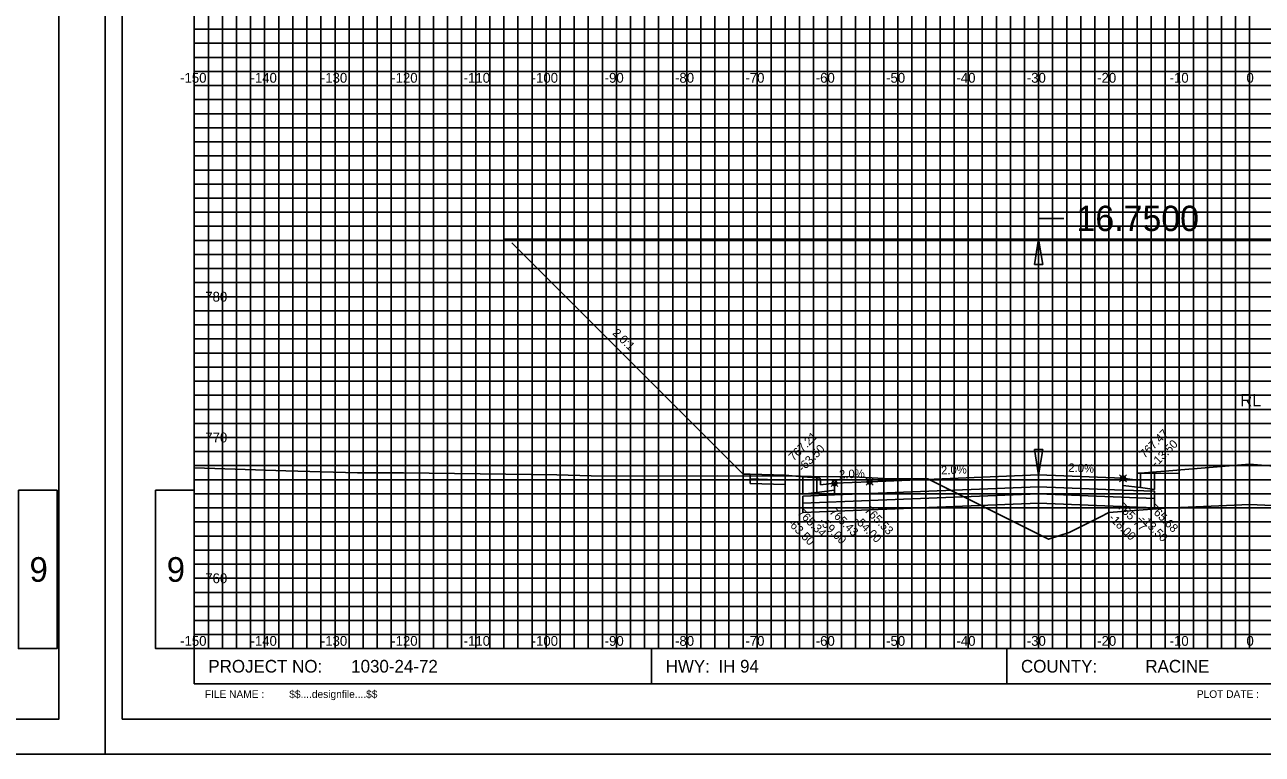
# Model space of a CAD drawing. Extents: x 578243 to 601557, y 174899 to 175559.
# Drawn here: x 600865.7 to 601041.6, y 174898.8 to 175002.4 of the extents above; entities that cross this region are included whole.
import ezdxf

# ---------------------------------------------------------------- set-up
doc = ezdxf.new("R2010")
doc.units = 0
for name, color, linetype in [('E_PROF_Grid', 7, 'Continuous'), ('E_PROF_GridMin', 7, 'Continuous'), ('P_CRDR_Label', 7, 'Continuous'), ('P_CRDR_Link', 7, 'Continuous'), ('P_E_XS_Ground', 7, 'Continuous'), ('P_RW_SlopeIntercepts', 7, 'Continuous'), ('P_XS_Text', 7, 'Continuous'), ('PLT_Sheet_Border', 7, 'Continuous'), ('PLT_Sheet_Info', 7, 'Continuous')]:
    doc.layers.add(name, color=color, linetype=linetype)

msp = doc.modelspace()

# ---------------------------------------------------------------- linework, layer by layer
at = {"layer": 'E_PROF_Grid'}
for p, q in [((600899.84, 174913.8), (600899.84, 175108.8)), ((600909.84, 174913.8), (600909.84, 175108.8)), ((600919.84, 174913.8), (600919.84, 175108.8)), ((600929.84, 174913.8), (600929.84, 175108.8)), ((600939.84, 174913.8), (600939.84, 175108.8)), ((600949.84, 174913.8), (600949.84, 175108.8)), ((600959.84, 174913.8), (600959.84, 175108.8)), ((600969.84, 174913.8), (600969.84, 175108.8)), ((600979.84, 174913.8), (600979.84, 175108.8)), ((600989.84, 174913.8), (600989.84, 175108.8)), ((600999.84, 174913.8), (600999.84, 175108.8)), ((601009.84, 174913.8), (601009.84, 175108.8)), ((601019.84, 174913.8), (601019.84, 175108.8)), ((601029.84, 174913.8), (601029.84, 175108.8)), ((601039.84, 174913.8), (601039.84, 175108.8)), ((600889.84, 174993.8), (601204.84, 174993.8)), ((600889.84, 174983.8), (601204.84, 174983.8)), ((600889.84, 174973.8), (601204.84, 174973.8)), ((600889.84, 174963.8), (601204.84, 174963.8)), ((600889.84, 174953.8), (601204.84, 174953.8)), ((600889.84, 174943.8), (601204.84, 174943.8)), ((600889.84, 174933.8), (601204.84, 174933.8)), ((600889.84, 174923.8), (601204.84, 174923.8))]:
    msp.add_line(p, q, dxfattribs=at)
at = {"layer": 'E_PROF_GridMin'}
for p, q in [((600891.84, 174913.8), (600891.84, 175108.8)), ((600893.84, 174913.8), (600893.84, 175108.8)), ((600895.84, 174913.8), (600895.84, 175108.8)), ((600897.84, 174913.8), (600897.84, 175108.8)), ((600901.84, 174913.8), (600901.84, 175108.8)), ((600903.84, 174913.8), (600903.84, 175108.8)), ((600905.84, 174913.8), (600905.84, 175108.8)), ((600907.84, 174913.8), (600907.84, 175108.8)), ((600911.84, 174913.8), (600911.84, 175108.8)), ((600913.84, 174913.8), (600913.84, 175108.8)), ((600915.84, 174913.8), (600915.84, 175108.8)), ((600917.84, 174913.8), (600917.84, 175108.8)), ((600921.84, 174913.8), (600921.84, 175108.8)), ((600923.84, 174913.8), (600923.84, 175108.8)), ((600925.84, 174913.8), (600925.84, 175108.8)), ((600927.84, 174913.8), (600927.84, 175108.8)), ((600931.84, 174913.8), (600931.84, 175108.8)), ((600933.84, 174913.8), (600933.84, 175108.8)), ((600935.84, 174913.8), (600935.84, 175108.8)), ((600937.84, 174913.8), (600937.84, 175108.8)), ((600941.84, 174913.8), (600941.84, 175108.8)), ((600943.84, 174913.8), (600943.84, 175108.8)), ((600945.84, 174913.8), (600945.84, 175108.8)), ((600947.84, 174913.8), (600947.84, 175108.8)), ((600951.84, 174913.8), (600951.84, 175108.8)), ((600953.84, 174913.8), (600953.84, 175108.8)), ((600955.84, 174913.8), (600955.84, 175108.8)), ((600957.84, 174913.8), (600957.84, 175108.8)), ((600961.84, 174913.8), (600961.84, 175108.8)), ((600963.84, 174913.8), (600963.84, 175108.8)), ((600965.84, 174913.8), (600965.84, 175108.8)), ((600967.84, 174913.8), (600967.84, 175108.8)), ((600971.84, 174913.8), (600971.84, 175108.8)), ((600973.84, 174913.8), (600973.84, 175108.8)), ((600975.84, 174913.8), (600975.84, 175108.8)), ((600977.84, 174913.8), (600977.84, 175108.8)), ((600981.84, 174913.8), (600981.84, 175108.8)), ((600983.84, 174913.8), (600983.84, 175108.8)), ((600985.84, 174913.8), (600985.84, 175108.8)), ((600987.84, 174913.8), (600987.84, 175108.8)), ((600991.84, 174913.8), (600991.84, 175108.8)), ((600993.84, 174913.8), (600993.84, 175108.8)), ((600995.84, 174913.8), (600995.84, 175108.8)), ((600997.84, 174913.8), (600997.84, 175108.8)), ((601001.84, 174913.8), (601001.84, 175108.8)), ((601003.84, 174913.8), (601003.84, 175108.8)), ((601005.84, 174913.8), (601005.84, 175108.8)), ((601007.84, 174913.8), (601007.84, 175108.8)), ((601011.84, 174913.8), (601011.84, 175108.8)), ((601013.84, 174913.8), (601013.84, 175108.8)), ((601015.84, 174913.8), (601015.84, 175108.8)), ((601017.84, 174913.8), (601017.84, 175108.8)), ((601021.84, 174913.8), (601021.84, 175108.8)), ((601023.84, 174913.8), (601023.84, 175108.8)), ((601025.84, 174913.8), (601025.84, 175108.8)), ((601027.84, 174913.8), (601027.84, 175108.8)), ((601031.84, 174913.8), (601031.84, 175108.8)), ((601033.84, 174913.8), (601033.84, 175108.8)), ((601035.84, 174913.8), (601035.84, 175108.8)), ((601037.84, 174913.8), (601037.84, 175108.8)), ((600889.84, 175001.8), (601204.84, 175001.8)), ((600889.84, 174999.8), (601204.84, 174999.8)), ((600889.84, 174997.8), (601204.84, 174997.8)), ((600889.84, 174995.8), (601204.84, 174995.8)), ((600889.84, 174991.8), (601204.84, 174991.8)), ((600889.84, 174989.8), (601204.84, 174989.8)), ((600889.84, 174987.8), (601204.84, 174987.8)), ((600889.84, 174985.8), (601204.84, 174985.8)), ((600889.84, 174981.8), (601204.84, 174981.8)), ((600889.84, 174979.8), (601204.84, 174979.8)), ((600889.84, 174977.8), (601204.84, 174977.8)), ((600889.84, 174975.8), (601204.84, 174975.8)), ((600889.84, 174971.8), (601204.84, 174971.8)), ((600889.84, 174969.8), (601204.84, 174969.8)), ((600889.84, 174967.8), (601204.84, 174967.8)), ((600889.84, 174965.8), (601204.84, 174965.8)), ((600889.84, 174961.8), (601204.84, 174961.8)), ((600889.84, 174959.8), (601204.84, 174959.8)), ((600889.84, 174957.8), (601204.84, 174957.8)), ((600889.84, 174955.8), (601204.84, 174955.8)), ((600889.84, 174951.8), (601204.84, 174951.8)), ((600889.84, 174949.8), (601204.84, 174949.8)), ((600889.84, 174947.8), (601204.84, 174947.8)), ((600889.84, 174945.8), (601204.84, 174945.8)), ((600889.84, 174941.8), (601204.84, 174941.8)), ((600889.84, 174939.8), (601204.84, 174939.8)), ((600889.84, 174937.8), (601204.84, 174937.8)), ((600889.84, 174935.8), (601204.84, 174935.8)), ((600889.84, 174931.8), (601204.84, 174931.8)), ((600889.84, 174929.8), (601204.84, 174929.8)), ((600889.84, 174927.8), (601204.84, 174927.8)), ((600889.84, 174925.8), (601204.84, 174925.8)), ((600889.84, 174921.8), (601204.84, 174921.8)), ((600889.84, 174919.8), (601204.84, 174919.8)), ((600889.84, 174917.8), (601204.84, 174917.8)), ((600889.84, 174915.8), (601204.84, 174915.8)), ((600877.19, 174898.8), (600877.19, 174908.8)), ((600867.19, 174898.8), (600877.19, 174898.8))]:
    msp.add_line(p, q, dxfattribs=at)
at = {"layer": 'P_CRDR_Label'}
for points in [[(601039.84, 174947.61), (601039.84, 174939.99)], [(600985.34, 174937.02), (600986.33, 174938.01)], [(600985.34, 174938.01), (600986.33, 174937.02)], [(601021.34, 174937.5), (601022.33, 174938.49)], [(601021.34, 174938.49), (601022.33, 174937.5)], [(600980.34, 174936.82), (600981.33, 174937.81)], [(600980.34, 174937.81), (600981.33, 174936.82)]]:
    msp.add_lwpolyline(points, dxfattribs=at)
for centre in [(601021.84, 174938), (600980.84, 174937.32), (600985.84, 174937.52)]:
    msp.add_circle(centre, 0.35, dxfattribs=at)
at = {"layer": 'P_CRDR_Link'}
msp.add_line((600934.99, 174971.46), (600967.84, 174938.61), dxfattribs=at)
for points in [[(601024.34, 174938.75), (601039.84, 174939.99)], [(601024.34, 174938.75), (601039.84, 174939.99)], [(601055.34, 174938.75), (601039.84, 174939.99)], [(601055.34, 174938.75), (601039.84, 174939.99)], [(600968.84, 174938.58), (600967.84, 174938.61)], [(600968.84, 174938.58), (600967.84, 174938.61)], [(600973.84, 174938.43), (600968.84, 174938.58)], [(600973.84, 174938.43), (600968.84, 174938.58)], [(600968.84, 174938.58), (600968.84, 174937.91)], [(600973.83, 174937.76), (600968.84, 174937.91)], [(600968.85, 174937.25), (600968.84, 174937.91)], [(600973.84, 174938.43), (600973.83, 174937.76)], [(600976.34, 174938.23), (600973.84, 174938.43)], [(600976.34, 174938.23), (600973.84, 174938.43)], [(600978.34, 174938.07), (600976.34, 174938.23)], [(600976.34, 174938.23), (600976.34, 174935.75)], [(600976.34, 174938.23), (600976.34, 174935.75)], [(600976.34, 174938.23), (600976.34, 174935.75)], [(600978.66, 174938.07), (600978.34, 174938.07)], [(600978.66, 174938.07), (600978.34, 174938.07)], [(600978.34, 174938.07), (600978.34, 174936)], [(600978.34, 174936), (600978.34, 174938.07)], [(600978.74, 174938.02), (600978.66, 174938.07)], [(600978.74, 174938.02), (600978.66, 174938.07)], [(600978.8, 174937.91), (600978.74, 174938.02)], [(600978.8, 174937.91), (600978.74, 174938.02)], [(600978.83, 174937.75), (600978.8, 174937.91)], [(600978.83, 174937.75), (600978.8, 174937.91)], [(601009.84, 174938.48), (600985.84, 174937.52)], [(601021.84, 174938), (601009.84, 174938.48)], [(601009.84, 174938.48), (601009.84, 174936.81)], [(601009.84, 174938.48), (601009.84, 174936.81)], [(601021.84, 174938), (601023.84, 174937.75)], [(601021.84, 174938), (601023.84, 174937.75)], [(601021.84, 174937), (601021.84, 174938)], [(601021.84, 174938), (601021.84, 174936.33)], [(601023.84, 174937.75), (601023.85, 174938.43)], [(601023.84, 174937.75), (601023.85, 174938.43)], [(601023.85, 174938.43), (601023.88, 174938.59)], [(601023.85, 174938.43), (601023.88, 174938.59)], [(601023.88, 174938.59), (601023.94, 174938.7)], [(601023.88, 174938.59), (601023.94, 174938.7)], [(601023.94, 174938.7), (601024.02, 174938.75)], [(601023.94, 174938.7), (601024.02, 174938.75)], [(601024.02, 174938.75), (601024.34, 174938.75)], [(601024.02, 174938.75), (601024.34, 174938.75)], [(601024.34, 174938.75), (601024.34, 174936.68)], [(601024.34, 174938.75), (601026.34, 174938.73)], [(601024.34, 174936.68), (601024.34, 174938.75)], [(601026.34, 174938.73), (601026.34, 174936.43)], [(601026.34, 174938.73), (601026.34, 174936.43)], [(601026.34, 174938.73), (601026.34, 174936.43)], [(601026.34, 174938.73), (601029.84, 174938.7)], [(601026.34, 174938.73), (601029.84, 174938.7)], [(600973.83, 174937.1), (600968.85, 174937.25)], [(600973.83, 174937.76), (600973.83, 174937.1)], [(600978.34, 174936), (600980.84, 174936.32)], [(600978.34, 174936), (600980.84, 174936.32)], [(600978.84, 174937.07), (600978.83, 174937.75)], [(600978.84, 174937.07), (600978.83, 174937.75)], [(600980.84, 174937.32), (600978.84, 174937.07)], [(600980.84, 174937.32), (600978.84, 174937.07)], [(600985.84, 174937.52), (600980.84, 174937.32)], [(600980.84, 174937.32), (600980.84, 174935.65)], [(600980.84, 174936.32), (600980.84, 174937.32)], [(600985.84, 174937.52), (600985.84, 174935.85)], [(600985.84, 174937.52), (600985.84, 174935.85)], [(601009.84, 174936.81), (600985.84, 174935.85)], [(601021.84, 174936.33), (601009.84, 174936.81)], [(601009.84, 174936.81), (601009.84, 174935.81)], [(601009.84, 174936.81), (601009.84, 174935.81)], [(601024.34, 174936.68), (601021.84, 174937)], [(601024.34, 174936.68), (601021.84, 174937)], [(601026.34, 174936.15), (601021.84, 174936.33)], [(601026.34, 174936.43), (601024.34, 174936.68)], [(601026.34, 174936.15), (601026.34, 174935.15)], [(600976.34, 174935.75), (600978.34, 174936)], [(600980.84, 174935.65), (600976.34, 174935.47)], [(600976.34, 174935.47), (600976.34, 174934.47)], [(600985.84, 174934.85), (600976.34, 174934.47)], [(600976.34, 174934.47), (600976.34, 174933.14)], [(600985.84, 174935.85), (600980.84, 174935.65)], [(600985.84, 174935.85), (600985.84, 174934.85)], [(600985.84, 174935.85), (600985.84, 174934.85)], [(601009.84, 174935.81), (600985.84, 174934.85)], [(600985.84, 174934.85), (600985.84, 174933.52)], [(600985.84, 174934.85), (600985.84, 174933.52)], [(601009.84, 174934.48), (600985.84, 174933.52)], [(601026.34, 174935.15), (601009.84, 174935.81)], [(601009.84, 174935.81), (601009.84, 174934.48)], [(601009.84, 174935.81), (601009.84, 174934.48)], [(601026.34, 174933.82), (601009.84, 174934.48)], [(601026.34, 174935.15), (601026.34, 174933.82)], [(600985.84, 174933.52), (600976.34, 174933.14)]]:
    msp.add_lwpolyline(points, dxfattribs=at)
at = {"layer": 'P_E_XS_Ground'}
msp.add_lwpolyline([(600889.84, 174939.49), (600889.89, 174939.49), (600902.84, 174939.04), (600913.06, 174938.79), (600915.72, 174938.8), (600919.59, 174938.76), (600941.38, 174938.5), (600946.25, 174938.37), (600957.78, 174938.3), (600964.22, 174938.33), (600975.98, 174938.3), (600977.57, 174938.26), (600983.54, 174938.21), (600987.87, 174937.97), (600989.2, 174937.93), (600994.11, 174937.92), (601011.27, 174929.34), (601014.2, 174930.31), (601018.54, 174932.49), (601019.84, 174933.14), (601022.84, 174933.38), (601027.84, 174933.78), (601039.84, 174934.26), (601051.84, 174933.78)], dxfattribs=at)
at = {"layer": 'P_RW_SlopeIntercepts'}
for p, q in [((601009.84, 174974.9), (601013.44, 174974.9)), ((601009.84, 174938.48), (601009.84, 174974.9)), ((600933.84, 174971.98), (601169.84, 174971.98)), ((601009.84, 174971.98), (601009.24, 174968.38)), ((601010.44, 174968.38), (601009.84, 174971.98)), ((601009.24, 174968.38), (601010.44, 174968.38)), ((601009.24, 174942.08), (601010.44, 174942.08)), ((601009.84, 174938.48), (601009.24, 174942.08)), ((601010.44, 174942.08), (601009.84, 174938.48))]:
    msp.add_line(p, q, dxfattribs=at)
at = {"layer": 'PLT_Sheet_Border'}
for points in [[(600537.19, 174898.8), (600877.19, 174898.8), (600877.19, 175118.8), (600537.19, 175118.8)], [(600877.19, 174898.8), (601217.19, 174898.8), (601217.19, 175118.8), (600877.19, 175118.8)], [(600539.59, 174903.8), (600870.59, 174903.8), (600870.59, 175113.8), (600539.59, 175113.8)], [(600879.59, 174903.8), (601210.59, 174903.8), (601210.59, 175113.8), (600879.59, 175113.8)]]:
    msp.add_lwpolyline(points, close=True, dxfattribs=at)
at = {"layer": 'PLT_Sheet_Info'}
for p, q in [((600889.84, 174908.8), (600889.84, 175108.8)), ((600889.84, 174913.8), (601204.84, 174913.8)), ((600954.84, 174908.8), (600954.84, 174913.8)), ((601005.34, 174908.8), (601005.34, 174913.8)), ((600877.19, 174898.8), (600877.19, 174908.8)), ((600889.84, 174908.8), (601204.84, 174908.8)), ((600877.19, 174898.8), (600887.19, 174898.8))]:
    msp.add_line(p, q, dxfattribs=at)
for points in [[(600864.84, 174936.3), (600870.34, 174936.3), (600870.34, 174913.8), (600864.84, 174913.8)], [(600889.84, 174936.3), (600884.34, 174936.3), (600884.34, 174913.8), (600889.84, 174913.8)]]:
    msp.add_lwpolyline(points, close=True, dxfattribs=at)

# ---------------------------------------------------------------- texts
at = {"layer": 'P_CRDR_Label'}
for s, rotation, p in [('2.0:1', 315.8532, (600949.19, 174958.54)), ('767.47', 45, (601024.93, 174940.77)), ('767.21', 45, (600975.03, 174940.38)), ('-13.50', 45, (601026.52, 174939.54)), ('-63.50', 45, (600976.34, 174938.86)), ('2.0%', 2.2906, (600996, 174938.54)), ('2.0%', 357.7094, (601014.05, 174938.93)), ('2.0%', 2.2906, (600981.5, 174937.96)), ('765.77', 315, (601020.99, 174933.85)), ('765.68', 315, (601025.49, 174933.67)), ('765.34', 315, (600975.49, 174932.99)), ('765.43', 315, (600980.03, 174933.14)), ('765.53', 315, (600985.02, 174933.34)), ('-63.50', 315, (600974.08, 174931.58)), ('-59.00', 315, (600978.58, 174931.76)), ('-54.00', 315, (600983.58, 174931.96)), ('-18.00', 315, (601019.73, 174932.29)), ('-13.50', 315, (601024.25, 174932.08))]:
    msp.add_text(s, height=1.2, rotation=rotation, dxfattribs=at).set_placement(p)
msp.add_text('RL', height=1.75, dxfattribs=at).set_placement((601038.51, 174948.24))
at = {"layer": 'P_RW_SlopeIntercepts'}
msp.add_text('16.7500', height=3.6, dxfattribs=at).set_placement((601015.24, 174973.13))
at = {"layer": 'P_XS_Text'}
for s, p in [('-150', (600887.83, 174994.2)), ('-140', (600897.83, 174994.2)), ('-130', (600907.83, 174994.2)), ('-120', (600917.83, 174994.2)), ('-110', (600928.13, 174994.2)), ('-100', (600937.79, 174994.2)), ('-90', (600948.17, 174994.2)), ('-80', (600958.17, 174994.2)), ('-70', (600968.17, 174994.2)), ('-60', (600978.17, 174994.2)), ('-50', (600988.17, 174994.2)), ('-40', (600998.17, 174994.2)), ('-30', (601008.17, 174994.2)), ('-20', (601018.17, 174994.2)), ('-10', (601028.47, 174994.2)), ('0', (601039.39, 174994.2)), ('0', (601039.39, 174994.2)), ('780', (600891.4, 174963.1)), ('770', (600891.4, 174943.1)), ('760', (600891.4, 174923.1)), ('-150', (600887.83, 174914.2)), ('-140', (600897.83, 174914.2)), ('-130', (600907.83, 174914.2)), ('-120', (600917.83, 174914.2)), ('-110', (600928.13, 174914.2)), ('-100', (600937.79, 174914.2)), ('-90', (600948.17, 174914.2)), ('-80', (600958.17, 174914.2)), ('-70', (600968.17, 174914.2)), ('-60', (600978.17, 174914.2)), ('-50', (600988.17, 174914.2)), ('-40', (600998.17, 174914.2)), ('-30', (601008.17, 174914.2)), ('-20', (601018.17, 174914.2)), ('-10', (601028.47, 174914.2)), ('0', (601039.39, 174914.2)), ('0', (601039.39, 174914.2))]:
    msp.add_text(s, height=1.4, rotation=360, dxfattribs=at).set_placement(p)
at = {"layer": 'PLT_Sheet_Info'}
for s, height, p in [('9', 3.5, (600866.42, 174923.3)), ('9', 3.5, (600885.92, 174923.3)), ('PROJECT NO:', 1.8, (600891.84, 174910.4)), ('1030-24-72             ', 1.8, (600912.14, 174910.4)), ('HWY:', 1.8, (600956.84, 174910.4)), ('IH 94               ', 1.8, (600964.34, 174910.4)), ('COUNTY:', 1.8, (601007.34, 174910.4)), ('       RACINE       ', 1.8, (601020.34, 174910.4)), ('FILE NAME :', 1.08, (600891.34, 174906.8))]:
    msp.add_text(s, height=height, dxfattribs=at).set_placement(p)
for s, p in [('$$....designfile....$$', (600903.34, 174906.8)), ('PLOT DATE :', (601032.34, 174906.8))]:
    msp.add_text(s, height=1.08, rotation=360, dxfattribs=at).set_placement(p)

doc.saveas('drawing.dxf')
